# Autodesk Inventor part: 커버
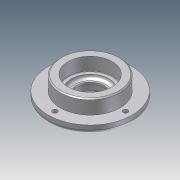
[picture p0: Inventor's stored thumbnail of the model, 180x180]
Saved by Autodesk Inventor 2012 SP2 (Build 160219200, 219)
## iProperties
Company: 한국ATC센터
Created: 2014-10
Part Number: 커버
Document SubType Name: Modeling
Designer: KYOUNG IL JANG
Density: 1 g/cm^3
Mass: 44.7286 g
Surface Area: 161.165 cm^2
Volume: 44.7286 cm^3
Material: 기본값
Author: KYOUNG IL JANG
Revision Number: 1
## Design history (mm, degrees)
sketch "스케치1"
  geometry: C1 r 38 at (0, 0); 1 further point
  constraints: 1 centre point, 1 coincident
  dimensions: "d0" = 76 diameter of C1
extrude "돌출1" new body sketch "스케치1" distance "d1" = 7; taper "d2" = 0 deg
sketch "스케치2"
  geometry: C1 r 27 at (0, 0); 1 further point
  constraints: 1 centre point, 1 coincident
  dimensions: "d3" = 54 diameter of C1
extrude "돌출2" join sketch "스케치2" distance "d4" = 13; taper "d5" = 0 deg
sketch "스케치3"
  geometry: C1 r 20 at (0, 0); 1 further point
  constraints: 1 centre point, 1 coincident
  dimensions: "d6" = 40 diameter of C1
extrude "돌출3" join sketch "스케치3" distance "d7" = 5; taper "d8" = 0 deg
hole "구멍1" diameter "d11" = 25; stored, may be unused: countersink angle "d15" = 90 deg, drill point angle "d17" = 118 deg; dims "d9" = 10, "d10" = 10, "d12" = 6, "d13" = 32, "d14" = 8.3, "d16" = 8
hole "구멍2" diameter "d20" = 34; stored, may be unused: countersink angle "d24" = 90 deg, drill point angle "d26" = 0 deg; dims "d18" = 10, "d19" = 10, "d21" = 6, "d22" = 40, "d23" = 12, "d25" = 3
fillet "모깎기2" dims "d34" = 3
fillet "모깎기1" dims "d27" = 0.3
chamfer "모따기1" distance "d28" = 1; stored, may be unused: second distance "d29" = 2, angle "d30" = 45 deg
chamfer "모따기2" distance "d31" = 1.2; stored, may be unused: second distance "d32" = 2, angle "d33" = 30 deg
sketch "스케치4" dims "d35" = 64
  geometry: 3 further points
  constraints: 2 horizontal alignment, 1 coincident, 2 other
hole "구멍3" sketch "스케치4" at (32, 0) diameter "d36" = 4.5; stored, may be unused: countersink angle "d40" = 90 deg, drill point angle "d42" = 118 deg; dims "d37" = 6, "d38" = 8, "d39" = 4.4, "d41" = 13
node "솔리드1"
pattern_circular "원형 패턴1" dims angle "d44" = 360 deg
